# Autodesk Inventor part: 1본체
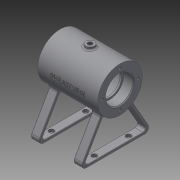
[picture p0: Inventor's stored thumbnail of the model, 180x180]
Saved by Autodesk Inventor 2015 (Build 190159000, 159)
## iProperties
Created: 2016-03
Part Number: 1본체
Material: 일반
Document SubType Name: Modeling
Designer: Administrator
Density: 1 g/cm^3
Appearance: 기본값
Author: Administrator
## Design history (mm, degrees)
sketch "스케치1"
  geometry: C1 r 26 at (0, 0); 1 further point
  constraints: 1 centre point, 1 coincident
  dimensions: "d0" = 52 diameter of C1
extrude "돌출1" new body sketch "스케치1" distance "d1" = 70; taper "d2" = 0 deg
node "작업 평면2"
  node "작업 평면1"
sketch "스케치2"
  geometry: L1 (-33.934, -65)-(33.934, -65); L2 (16.613, -20)-(38.264, -57.5); L3 (-16.613, -20)-(-38.264, -57.5); L4 (14.183, -21.791)-(34.8, -57.5); L5 (-14.183, -21.791)-(-34.8, -57.5); L6 (-32.202, -62)-(32.202, -62); A1 r 26 centre (0, 0) between (16.613, -20) and (-16.613, -20) reference; A2 r 5 centre (-33.934, -60) between (-38.264, -57.5) and (-33.934, -65); A3 r 5 centre (33.934, -60) between (33.934, -65) and (38.264, -57.5); A4 r 3 centre (-32.202, -59) between (-34.8, -57.5) and (-32.202, -62); A5 r 3 centre (32.202, -59) between (32.202, -62) and (34.8, -57.5); 1 further point
  constraints: 12 end point, 12 point on circle, 8 tangent, 4 centre point, 2 equal radius, 2 horizontal
  dimensions: "d5" = 65 distance from line of point (0, 0) L1; "d8" = 5 radius of A2; "d10" = 3 distance between parallel lines of L4 L2; "d11" = 3 distance between parallel lines of L6 L1; "d46" = 3 radius of A4
extrude "돌출2" join sketch "스케치2" distance "d13" = 10; taper "d14" = 0 deg
node "작업 평면3"
sketch "스케치4"
  geometry: L1 (0, 10)-(67.868, 10) reference; L2 (33.934, 10)-(33.934, 37.245); L3 (0, -40)-(67.868, -40) reference; L4 (0, -50)-(67.868, -50) reference; C1 r 3 at (13.934, 5); C2 r 3 at (53.934, 5); C3 r 3 at (13.934, -45); C4 r 3 at (53.934, -45); 1 further point
  constraints: 4 centre point, 2 end point, 1 midpoint, 1 vertical
  dimensions: "d15" = 6 diameter of C1; "d16" = 20 distance from line of L2 C1.centre; "d17" = 5 distance from line of L1 C1.centre; "d18" = 6 diameter of C2; "d19" = 40 distance of C1.centre C2.centre; "d20" = 6 diameter of C3; "d21" = 6 diameter of C4; "d22" = 5 distance from line of L3 C4.centre; "d23" = 40 distance of C3.centre C4.centre; "d24" = 5 distance from line of L4 C3.centre; "d25" = 20 distance from line of C3.centre L2
extrude "돌출3" cut sketch "스케치4" stored distance "d26" = 10; taper "d27" = 0 deg
fillet "모깎기1" dims "d28" = 0.5
sketch "스케치5"
  geometry: L1 (0, 0)-(0, 70); L2 (16, 70)-(0, 70); L3 (0, 0)-(16, 0); L4 (16, 70)-(16, 58.3); L5 (14, 58)-(14, 56); L6 (21, 53)-(21, 17); L7 (16, 0)-(16, 11.7); L8 (14, 12)-(14, 14); L9 (14, 12)-(15.7, 12); L10 (14, 14)-(18, 14); L11 (14, 56)-(18, 56); L12 (14, 58)-(15.7, 58); A1 r 0.3 centre (15.7, 58.3) between (15.7, 58) and (16, 58.3); A2 r 0.3 centre (15.7, 11.7) between (16, 11.7) and (15.7, 12); A3 r 3 centre (18, 17) between (18, 14) and (21, 17); A4 r 3 centre (18, 53) between (21, 53) and (18, 56); 2 further points
  constraints: 24 end point, 8 point on circle, 8 tangent, 5 point on line, 4 centre point, 4 vertical, 3 horizontal, 2 equal radius, 1 perpendicular
  dimensions: "d36" = 42 distance of point (21, 56) point (21, 14); "d40" = 0.3 radius of A1; "d41" = 3 radius of A3
revolve "회전1" sketch "스케치5" stored, may be unused: angle "d42" = 90 deg
chamfer "모따기1" distance "d43" = 1; stored, may be unused: second distance "d44" = 2, angle "d45" = 45 deg
sketch "스케치7"
  geometry: C1 r 17 at (0, 0) reference; 5 further points
  constraints: 1 coincident, 1 vertical alignment, 7 other
  dimensions: "d50" = 360 deg dimension on point (0, 0) point (0, 21) (derived)
hole "구멍1" sketch "스케치7" at (0, 21), (-21, 0), (0, -21), (21, 0) diameter "d52" = 3.242; stored, may be unused: countersink angle "d56" = 90 deg, drill point angle "d58" = 118 deg; dims "d53" = 8, "d54" = 4, "d55" = 2, "d57" = 10
node "작업 평면4"
sketch "스케치8"
  geometry: C1 r 5 at (0, 35); 1 further point
  constraints: 1 centre point
  dimensions: "d59" = 10 diameter of C1; "d60" = 35 distance of point (0, 0) C1.centre
extrude "돌출4" join sketch "스케치8" distance "d61" = 3; taper "d63" = 0 deg; dims "d62" = 5, "d64" = 0
fillet "모깎기2" dims "d65" = 2
sketch "스케치10"
  geometry: C1 r 5 at (0, 0) reference; 2 further points
  constraints: 1 coincident
hole "구멍2" sketch "스케치10" at (0, 0) diameter "d66" = 5.188; stored, may be unused: countersink angle "d70" = 90 deg, drill point angle "d72" = 118 deg; dims "d67" = 12, "d68" = 4, "d69" = 2, "d71" = 16
node "작업 평면5"
sketch "스케치13"
  geometry: L1 (-0.611, 55.739)-(-0.611, 14.261); L2 (-0.611, 14.261)-(0.611, 14.261); L3 (0.611, 14.261)-(0.611, 55.739); L4 (0.611, 55.739)-(-0.611, 55.739); L5 (0.611, 35)-(-19.284, 35); L6 (0, 55.739)-(0, 73.726); L7 (26, 70)-(-26, 70) reference; L8 (26, 0)-(26, 70) reference; 1 further point
  constraints: 4 end point, 2 midpoint, 1 horizontal, 1 vertical, 2 other
  dimensions: "d73" = 35 distance between parallel lines of L7 L5; "d74" = 26 distance between parallel lines of L8 L6
feature "엠보싱1" sketch "스케치13" dims "d1" = 70, "d2" = 0, "d75" = 0.5, "d76" = 0
node "작업 평면6"
sketch "스케치16"
  geometry: L1 (0, 0)-(0, 3) reference; L2 (-31.942, 3)-(0, 3) reference; L3 (-31.942, 0)-(-31.942, 3) reference; L4 (0, 0)-(-31.942, 0) reference; C1 r 6 at (0, 0); 1 further point
  constraints: 1 centre point, 1 coincident
  dimensions: "d83" = 12 diameter of C1
extrude "돌출6" join sketch "스케치16" distance "d84" = 4; taper "d85" = 0 deg
fillet "모깎기3" dims "d86" = 2
sketch "스케치17"
  geometry: C1 r 6 at (0, 0) reference; 2 further points
  constraints: 1 coincident
hole "구멍3" sketch "스케치17" at (0, 0) diameter "d87" = 5.188; stored, may be unused: countersink angle "d91" = 90 deg, drill point angle "d93" = 118 deg; dims "d88" = 12, "d89" = 4, "d90" = 2, "d92" = 16
fillet "모깎기4" dims "d94" = 3
node "솔리드1"
mirror "대칭1"
mirror "대칭2"
node "투영된 루프1"
